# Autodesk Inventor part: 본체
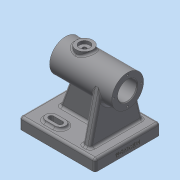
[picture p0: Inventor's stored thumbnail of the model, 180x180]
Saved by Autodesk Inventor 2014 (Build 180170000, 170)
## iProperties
Created: 2026-09
Part Number: 본체
Material: 일반
Document SubType Name: Modeling
Designer: dg
Density: 1 g/cm^3
Appearance: 기본값
Author: dg
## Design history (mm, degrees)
sketch "스케치1"
  geometry: L1 (-50, -43)-(50, -43); L2 (50, -43)-(50, 43); L3 (50, 43)-(-50, 43); L4 (-50, 43)-(-50, -43); L5 (-50, -43)-(50, 43); L6 (50, -43)-(-50, 43); 1 further point
  constraints: 12 end point, 2 midpoint, 2 parallel, 1 horizontal, 1 perpendicular
  dimensions: "d0" = 100 distance of L1.start L1.end; "d1" = 86 distance of L1.end L2.end
extrude "돌출1" new body sketch "스케치1" distance "d2" = 15; taper "d3" = 0 deg
node "작업 평면1"
sketch "스케치2"
  geometry: L1 (32, 21)-(-50, 21); L2 (-50, 21)-(-50, 0); L3 (-50, 0)-(32, 0); L4 (32, 0)-(32, 21); 2 further points
  constraints: 8 end point, 2 parallel, 1 horizontal, 1 horizontal alignment, 1 perpendicular, 1 vertical alignment
  dimensions: "d5" = 82 distance of L1.start L1.end; "d6" = 21 distance between parallel lines of L3 L1
revolve "회전1" sketch "스케치2" stored, may be unused: angle "d7" = 90 deg
node "작업 평면2"
sketch "스케치3"
  geometry: L1 (0, 0)-(-15, 0) reference; L2 (-15, 0)-(-15, 86) reference; L3 (-15, 86)-(0, 86) reference; L4 (0, 86)-(0, 0) reference; L5 (-76.814, 22.559)-(-15, 8); L6 (-76.814, 63.441)-(-15, 78); A1 r 21 centre (-72, 43) between (-76.814, 22.559) and (-76.814, 63.441) reference; 1 further point
  constraints: 4 end point, 2 point on circle, 2 point on line, 2 tangent
  dimensions: "d9" = 8 distance of L1.end L5.end; "d10" = 8 distance of L2.end L6.end
extrude "돌출2" join sketch "스케치3" distance "d11" = 10; taper "d12" = 0 deg
sketch "스케치4"
  geometry: L1 (-50, 0)-(-50, 15) reference; L2 (-50, 15)-(-35, 15) reference; L3 (-25, 51)-(-25, 15) reference; L4 (-35, 51)-(-50, 51) reference; L5 (-50, 51)-(-50, 93) reference; L6 (-50, 93)-(32, 93) reference; L7 (32, 93)-(32, 51) reference; L8 (32, 51)-(-25, 51) reference; L9 (-35, 15)-(-35, 51) reference; L10 (-25, 15)-(50, 15) reference; L11 (50, 15)-(50, 0) reference; L12 (50, 0)-(-50, 0) reference; L13 (35, 15)-(16.801, 65); L14 (16.801, 65)-(-30, 65); L15 (-30, 65)-(-30, 15); L16 (-30, 15)-(35, 15); 1 further point
  constraints: 8 end point, 2 parallel, 1 perpendicular, 1 point on line
  dimensions: "d13" = 70 deg angle of L10 L13; "d14" = 15 distance of L10.end L13.start; "d15" = 65 distance from line of L13.start L15; "d16" = 50 distance between parallel lines of L10 L14
extrude "돌출3" join sketch "스케치4" stored distance "d17" = 10; taper "d18" = 0 deg
hole "구멍1" diameter "d21" = 25; stored, may be unused: countersink angle "d25" = 90 deg, drill point angle "d27" = 118 deg; dims "d19" = 10, "d20" = 10, "d22" = 6, "d23" = 29, "d24" = 62, "d26" = 200
node "작업 평면3"
sketch "스케치5"
  geometry: L1 (32, -21)-(32, 21) reference; C1 r 11 at (7, 0); 1 further point
  constraints: 1 centre point, 1 horizontal alignment
  dimensions: "d29" = 22 diameter of C1; "d30" = 25 distance from line of L1 C1.centre
extrude "돌출4" join sketch "스케치5" stored distance "d31" = 10; taper "d32" = 0 deg
hole "구멍2" diameter "d35" = 4.917; stored, may be unused: countersink angle "d39" = 90 deg, drill point angle "d41" = 118 deg; dims "d33" = 10, "d34" = 10, "d36" = 6, "d37" = 14, "d38" = 4, "d40" = 20
sketch "스케치6"
  geometry: L1 (-50, 43)-(-50, -43) reference; L2 (-24, -27)-(-12, -27); L3 (-24, -34)-(-12, -34); L4 (-12, -20)-(-24, -20); A1 r 7 centre (-24, -27) between (-24, -20) and (-24, -34); A2 r 7 centre (-12, -27) between (-12, -34) and (-12, -20); 2 further points
  constraints: 8 end point, 4 point on circle, 4 tangent, 2 centre point, 1 midpoint, 1 parallel, 1 perpendicular
  dimensions: "d42" = 26 distance from line of L1 L2.start; "d43" = 12 distance of L2.end L2.start; "d44" = 14 distance of L3.start L4.end; "d45" = 27 vertical distance of point (0, 0) point (-18, -27)
extrude "돌출5" join sketch "스케치6" distance "d46" = 3; taper "d47" = 0 deg
sketch "스케치7"
  geometry: L1 (-24, -34)-(-12, -34) reference; L2 (-24, -27)-(-12, -27); L3 (-24, -23.7)-(-12, -23.7); L4 (-12, -30.3)-(-24, -30.3); A1 r 7 centre (-12, -27) between (-12, -34) and (-12, -20) reference; A2 r 7 centre (-24, -27) between (-24, -20) and (-24, -34) reference; A3 r 3.3 centre (-24, -27) between (-24, -23.7) and (-24, -30.3); A4 r 3.3 centre (-12, -27) between (-12, -30.3) and (-12, -23.7); 2 further points
  constraints: 8 end point, 4 point on circle, 4 tangent, 2 centre point, 2 parallel, 1 midpoint
  dimensions: "d48" = 6.6 distance of L4.end L3.start
extrude "돌출6" cut sketch "스케치7" stored distance "d49" = 3; taper "d50" = 0 deg
sketch "스케치8"
  geometry: C1 r 14.5 at (0, 0) reference; 2 further points
  constraints: 1 horizontal alignment
  dimensions: "d51" = 18 distance of C1.centre point (18, 0)
hole "구멍3" sketch "스케치8" at (18, 0) diameter "d52" = 2.459; stored, may be unused: countersink angle "d56" = 90 deg, drill point angle "d58" = 118 deg; dims "d53" = 8, "d54" = 14, "d55" = 4, "d57" = 10
node "작업 평면4"
fillet "모깎기1" dims "d62" = 3
fillet "모깎기3" dims "d64" = 3
fillet "모깎기4" dims "d65" = 3
chamfer "모따기1" distance "d67" = 1; stored, may be unused: second distance "d68" = 2, angle "d69" = 45 deg
sketch "스케치9"
  geometry: L1 (0, 0)-(0, 80) reference; 3 further points
  constraints: 1 horizontal alignment, 1 midpoint, 1 other
  dimensions: "d70" = 6 distance from line of L1 point (-6, 40)
feature "엠보싱1" sketch "스케치9" dims "d0" = 100, "d1" = 86, "d71" = 0.5, "d72" = 0
fillet "모깎기7" dims "d74" = 3
fillet "모깎기8" dims "d75" = 3
node "솔리드1"
mirror "대칭1"
pattern_circular "원형 패턴1" dims angle "d60" = 360 deg
mirror "대칭2"
node "절단 모서리 투영1"
node "절단 모서리 투영2"
other parameters: "d4" = -72, "d8" = -15, "d28" = -96
